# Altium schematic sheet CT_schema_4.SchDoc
size 296 x 173 mm
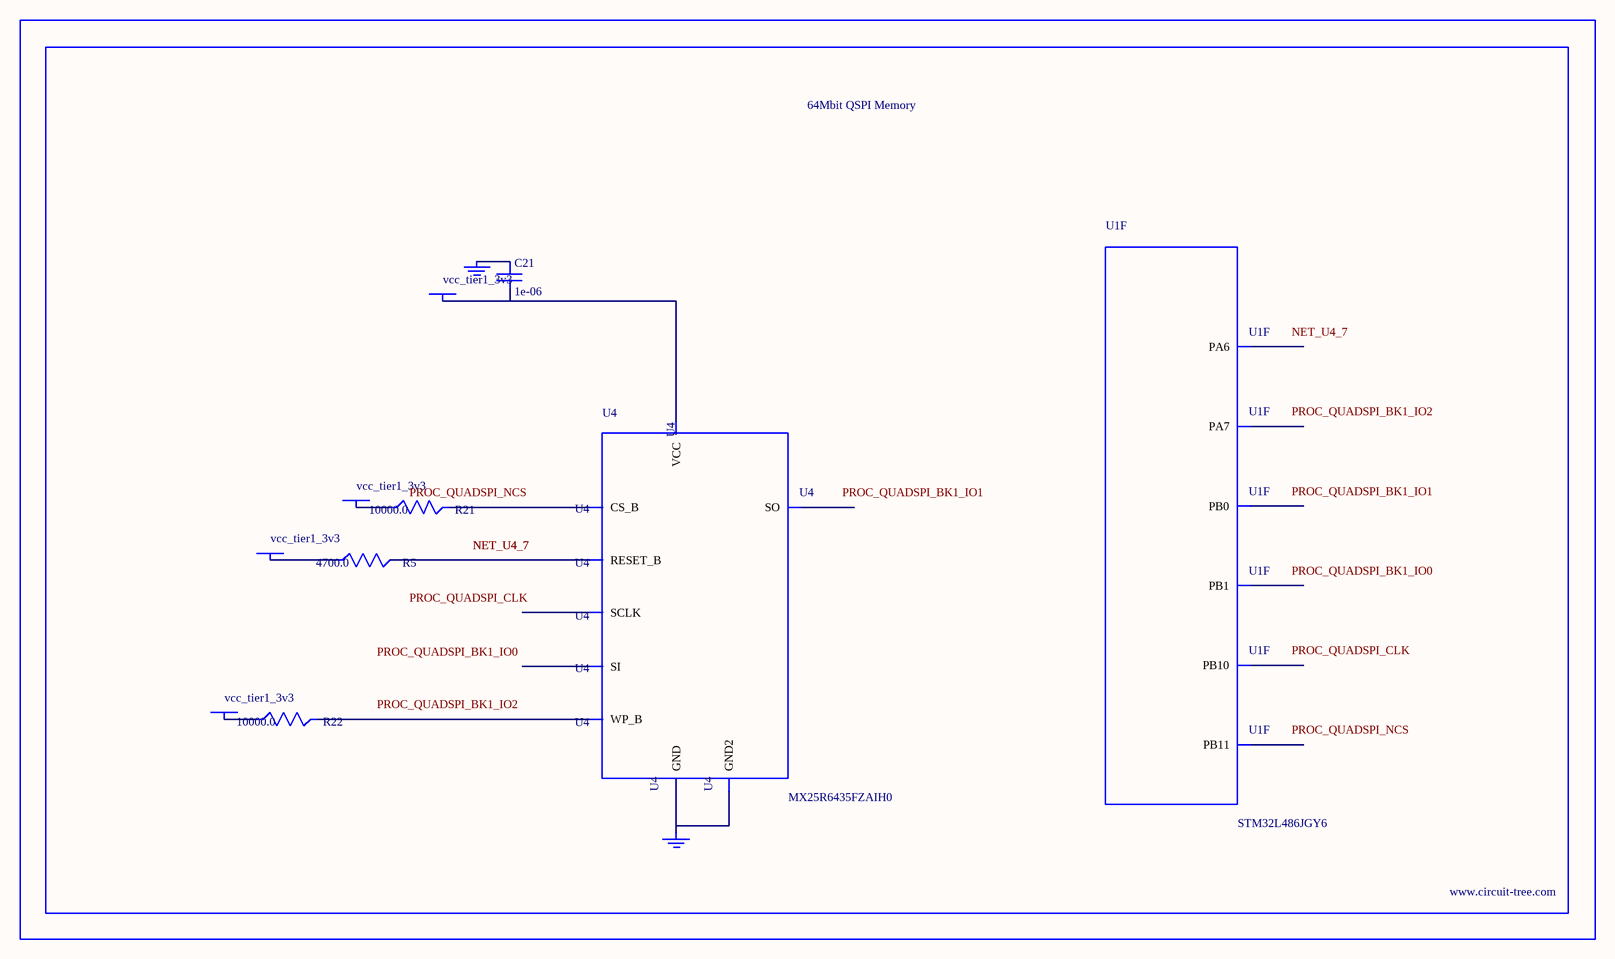
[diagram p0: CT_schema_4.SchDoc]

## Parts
BORDER3  (no value)
C21  1e-06  [C0603]
GND_INSTANCE_3_0  (no value)
GND_INSTANCE_3_1  (no value)
POWER_INSTANCE_3_0  vcc_tier1_3v3
POWER_INSTANCE_3_1  vcc_tier1_3v3
POWER_INSTANCE_3_2  vcc_tier1_3v3
POWER_INSTANCE_3_3  vcc_tier1_3v3
R5  4700.0  [R0603]
R21  10000.0  [R0603]
R22  10000.0  [R0603]
U1  STM32L486JGY6  [WLCSP72]  (part F of 7)
U4  MX25R6435FZAIH0  [WSON-8-PAD]

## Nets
NetC21_1: C21.1 GND_INSTANCE_3_0.0(GND)
NetC21_2: C21.2 POWER_INSTANCE_3_2.0(PWR) U4.8(VCC)
NetGND_INSTANCE_3_1_0: GND_INSTANCE_3_1.0(GND) U4.4(GND) U4.PAD(GND2)
NetPOWER_INSTANCE_3_0_0: POWER_INSTANCE_3_0.0(PWR) R21.1
NetPOWER_INSTANCE_3_1_0: POWER_INSTANCE_3_1.0(PWR) R22.1
NetPOWER_INSTANCE_3_3_0: POWER_INSTANCE_3_3.0(PWR) R5.1
NetR5_2: R5.2 U4.7(RESET_B)
NetR21_2: R21.2 U4.1(CS_B)
NetR22_2: R22.2 U4.3(WP_B)

Not connected (* = marked no-connect by the designer): U1 G3(PB11) H3(PB10) H4(PA7) H5(PA6) J4(PB1) J5(PB0); U4 2(SO) 5(SI) 6(SCLK)

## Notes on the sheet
- Labels drawn without touching a wire or pin: NET_U4_7, PROC_QUADSPI_BK1_IO0, PROC_QUADSPI_BK1_IO1, PROC_QUADSPI_BK1_IO2, PROC_QUADSPI_CLK, PROC_QUADSPI_NCS

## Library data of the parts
BORDER3 = BORDER_PAGE3
C21 = C0603C105K3RACTU
GND_INSTANCE_3_0 GND_INSTANCE_3_1 = GND
POWER_INSTANCE_3_0-POWER_INSTANCE_3_3 = PWR
R5 = RC0603JR-074K7L
R21 R22 = RC0603JR-0710KL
